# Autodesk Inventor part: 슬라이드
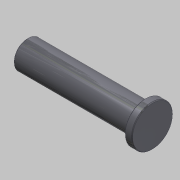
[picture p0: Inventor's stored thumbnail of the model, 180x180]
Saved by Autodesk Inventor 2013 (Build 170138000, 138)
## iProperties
Created: 2015-10
Part Number: 슬라이드
Document SubType Name: Modeling
Designer: mdu
Density: 1 g/cm^3
Material: 강철, 연강
Author: mdu
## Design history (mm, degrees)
sketch "스케치1"
  geometry: L1 (-75, 162)-(-75, 58) reference; L2 (-148, 110)-(22, 110); L3 (-148, 110)-(-148, 129); L4 (-148, 129)-(12, 129); L5 (12, 129)-(12, 138); L6 (12, 138)-(22, 138); L7 (22, 138)-(22, 110); 2 further points
  constraints: 12 end point, 3 parallel, 3 perpendicular, 1 midpoint, 1 point on line
  dimensions: "d0" = 56 diameter of L6 L2; "d1" = 38 diameter of L4 L2; "d2" = 10 distance of L5.end L6.end; "d3" = 170 distance of L2.start L2.end; "d4" = 73 distance between parallel lines of L3 L1
revolve "회전1" sketch "스케치1" stored, may be unused: angle "d5" = 90 deg
hole "구멍1" diameter "d11" = 13.376; stored, may be unused: countersink angle "d15" = 90 deg, drill point angle "d17" = 118 deg; dims "d9" = 10, "d10" = 10, "d12" = 22, "d13" = 4, "d14" = 2, "d16" = 25
chamfer "모따기1" distance "d6" = 1; stored, may be unused: second distance "d7" = 2, angle "d8" = 45 deg
node "솔리드1"
node "참조1"
